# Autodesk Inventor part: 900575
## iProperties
Created: 2007-12
Part Number: 900575
Document SubType Name: Modeling
Designer: GS
Density: 1.06 g/cm^3
Categories: <MemberInstance><Categories><Category DisplayName="" Mnemonic="CABLEANDHARNESS" InternalName="e4a7e005-5e42-4d16-b293-125e7f0d0512"><Category DisplayName="" Mne
Mass: 9.17765 g
Surface Area: 145.988 cm^2
Volume: 8.65816 cm^3
Material: ABS Plastic
Description: R9 MOTOR CONNECTOR
GlobalPropertyList: <PropertyList/>
Component Category: Electrical
Author: GS
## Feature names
1. Extrusion1
2. Extrusion2
3. Extrusion3
4. Extrusion4
5. Rectangular Pattern1
6. Fillet1
7. Extrusion5
8. Extrusion6
9. Extrusion7
10. Extrusion8
11. Chamfer1
12. Extrusion9
13. Extrusion10
14. Extrusion11
15. Rectangular Pattern2
16. Fillet2
17. Fillet3
